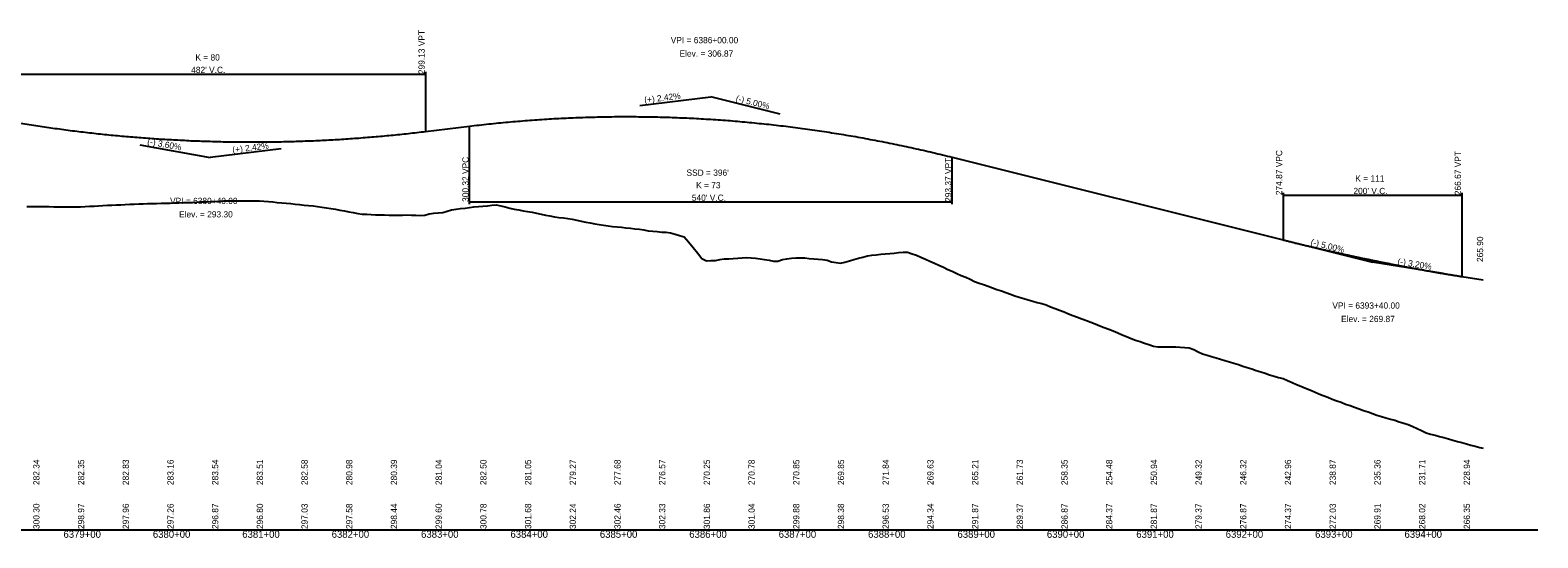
# Model space of a CAD drawing. Extents: x 1838386 to 1955906, y 719739 to 834437.
# Drawn here: x 1953520 to 1955206, y 770980 to 771548 of the extents above; entities that cross this region are included whole.
import ezdxf

# ---------------------------------------------------------------- set-up
doc = ezdxf.new("R2010")
doc.units = 0
for name, color, linetype in [('RD_DDB_GradeTX', 7, 'Continuous'), ('RD_DDB_Profile_EX', 7, 'Continuous'), ('RD_DDB_Profile_Lbl', 7, 'Continuous'), ('RD_DDB_Profile_PR', 7, 'Continuous'), ('RD_DDB_StaTX', 7, 'Continuous'), ('RD_DDB_StripGrade', 7, 'Continuous'), ('RD_DDB_VCLbl', 7, 'Continuous'), ('RD_GPK_Profile_Cell', 7, 'Continuous')]:
    doc.layers.add(name, color=color, linetype=linetype)

msp = doc.modelspace()

# ---------------------------------------------------------------- linework, layer by layer
at = {"layer": 'RD_DDB_GradeTX'}
for p, q in [((1954202, 771463.9), (1954281.4, 771473.5)), ((1954359, 771454.1), (1954281.4, 771473.5)), ((1953642.6, 771419.8), (1953721.4, 771405.6)), ((1953800.8, 771415.2), (1953721.4, 771405.6)), ((1954943.8, 771307.9), (1955021.4, 771288.5)), ((1955100.4, 771275.8), (1955021.4, 771288.5))]:
    msp.add_line(p, q, dxfattribs=at)
at = {"layer": 'RD_DDB_Profile_EX'}
for points in [[(1953516.4, 771350.7), (1953521.4, 771350.7), (1953526.4, 771350.7), (1953531.4, 771350.8), (1953536.4, 771350.7), (1953541.4, 771350.7), (1953546.4, 771350.6), (1953551.4, 771350.6), (1953556.4, 771350.6), (1953561.4, 771350.5), (1953566.4, 771350.5), (1953571.4, 771350.5), (1953576.4, 771350.6), (1953581.4, 771350.9), (1953586.4, 771351.2), (1953591.4, 771351.4), (1953596.4, 771351.7), (1953601.4, 771351.9), (1953606.4, 771352.2), (1953611.4, 771352.4), (1953616.4, 771352.6), (1953621.4, 771352.8), (1953626.4, 771353), (1953631.4, 771353.3), (1953636.4, 771353.5), (1953641.4, 771353.7), (1953646.4, 771353.9), (1953651.4, 771354.1), (1953656.4, 771354.2), (1953661.4, 771354.3), (1953666.4, 771354.4), (1953671.4, 771354.6), (1953676.4, 771354.7), (1953681.4, 771354.9), (1953686.4, 771355.1), (1953691.4, 771355.3), (1953696.4, 771355.4), (1953701.4, 771355.4), (1953706.4, 771355.6), (1953711.4, 771355.9), (1953716.4, 771356.1), (1953721.4, 771356.3), (1953726.4, 771356.6), (1953731.4, 771356.8), (1953736.4, 771357), (1953741.4, 771357.2), (1953746.4, 771357.2), (1953751.4, 771357.2), (1953756.4, 771357.1), (1953761.4, 771357), (1953766.4, 771357), (1953771.4, 771357), (1953776.4, 771357), (1953781.4, 771356.7), (1953786.4, 771356.4), (1953791.4, 771355.9), (1953796.4, 771355.4), (1953801.4, 771354.8), (1953806.4, 771354.4), (1953811.4, 771354.1), (1953816.4, 771353.6), (1953821.4, 771353.1), (1953826.4, 771352.5), (1953831.4, 771352), (1953836.4, 771351.6), (1953841.4, 771351), (1953846.4, 771350.2), (1953851.4, 771349.5), (1953856.4, 771348.7), (1953861.4, 771347.8), (1953866.4, 771346.9), (1953871.4, 771346), (1953876.4, 771345), (1953881.4, 771344), (1953886.4, 771343), (1953891.4, 771342.4), (1953896.4, 771342.1), (1953901.4, 771341.8), (1953906.4, 771341.5), (1953911.4, 771341.5), (1953916.4, 771341.4)], [(1953916.4, 771341.4), (1953921.4, 771341.2), (1953926.4, 771341.1), (1953931.4, 771341.1), (1953936.4, 771341.2), (1953941.4, 771341.4), (1953946.4, 771341.2), (1953951.4, 771341), (1953956.4, 771340.8), (1953961.4, 771341.2), (1953966.4, 771342.5), (1953971.4, 771343.4), (1953976.4, 771343.8), (1953981.4, 771344.3), (1953986.4, 771345.7), (1953991.4, 771347), (1953996.4, 771348), (1954001.4, 771348.5), (1954006.4, 771349.1), (1954011.4, 771349.7), (1954016.4, 771350.4), (1954021.4, 771350.7), (1954026.4, 771351.1), (1954031.4, 771351.6), (1954036.4, 771352.2), (1954041.4, 771352.6), (1954046.4, 771351.6), (1954051.4, 771350.4), (1954056.4, 771349.1), (1954061.4, 771347.8), (1954066.4, 771347), (1954071.4, 771346.1), (1954076.4, 771345.3), (1954081.4, 771344.4), (1954086.4, 771343.4), (1954091.4, 771342.4), (1954096.4, 771341.3), (1954101.4, 771340.3), (1954106.4, 771339.2), (1954111.4, 771338.5), (1954116.4, 771338.1), (1954121.4, 771337.6), (1954126.4, 771336.6), (1954131.4, 771335.5), (1954136.4, 771334.5), (1954141.4, 771333.4), (1954146.4, 771332.5), (1954151.4, 771331.6), (1954156.4, 771330.7), (1954161.4, 771329.9), (1954166.4, 771329.2), (1954171.4, 771328.6), (1954176.4, 771328.1), (1954181.4, 771327.6), (1954186.4, 771327), (1954191.4, 771326.5), (1954196.4, 771325.9), (1954201.4, 771325.3), (1954206.4, 771324.6), (1954211.4, 771323.8), (1954216.4, 771323.1), (1954221.4, 771322.7), (1954226.4, 771322.3), (1954231.4, 771322), (1954236.4, 771321.2), (1954241.4, 771319.8), (1954246.4, 771318.4), (1954251.4, 771317), (1954256.4, 771311.2), (1954261.4, 771305.1), (1954266.4, 771298.9), (1954271.4, 771292.7), (1954276.4, 771290), (1954281.4, 771290.4), (1954286.4, 771290.6), (1954291.4, 771291.6), (1954296.4, 771292.1), (1954301.4, 771292.3), (1954306.4, 771292.8), (1954311.4, 771293), (1954316.4, 771293.4), (1954321.4, 771293.8), (1954326.4, 771293.5), (1954331.4, 771293), (1954336.4, 771292.4), (1954341.4, 771291.7), (1954346.4, 771290.9), (1954351.4, 771289.7), (1954356.4, 771289.7), (1954361.4, 771291.6), (1954366.4, 771292.4), (1954371.4, 771293), (1954376.4, 771293.3), (1954381.4, 771293.4), (1954386.4, 771293.3), (1954391.4, 771292.8), (1954396.4, 771292.4), (1954401.4, 771291.9), (1954406.4, 771291.5), (1954411.4, 771290.8), (1954416.4, 771289.1)], [(1954416.4, 771289.1), (1954421.4, 771288.1), (1954426.4, 771287.6), (1954431.4, 771288.4), (1954436.4, 771290), (1954441.4, 771291.5), (1954446.4, 771292.9), (1954451.4, 771294.3), (1954456.4, 771295.7), (1954461.4, 771296.5), (1954466.4, 771296.9), (1954471.4, 771297.4), (1954476.4, 771297.9), (1954481.4, 771298.3), (1954486.4, 771298.8), (1954491.4, 771299.3), (1954496.4, 771299.8), (1954501.4, 771299.6), (1954506.4, 771297.9), (1954511.4, 771296.2), (1954516.4, 771294.1), (1954521.4, 771291.8), (1954526.4, 771289.6), (1954531.4, 771287.3), (1954536.4, 771285.1), (1954541.4, 771282.8), (1954546.4, 771280.5), (1954551.4, 771278.3), (1954556.4, 771276), (1954561.4, 771273.8), (1954566.4, 771271.6), (1954571.4, 771269.4), (1954576.4, 771267), (1954581.4, 771265.2), (1954586.4, 771263.4), (1954591.4, 771261.6), (1954596.4, 771259.9), (1954601.4, 771258.1), (1954606.4, 771256.3), (1954611.4, 771254.5), (1954616.4, 771252.8), (1954621.4, 771251), (1954626.4, 771249.4), (1954631.4, 771247.8), (1954636.4, 771246.4), (1954641.4, 771245), (1954646.4, 771243.6), (1954651.4, 771242.2), (1954656.4, 771240.7), (1954661.4, 771238.7), (1954666.4, 771236.7), (1954671.4, 771234.8), (1954676.4, 771232.8), (1954681.4, 771230.9), (1954686.4, 771229), (1954691.4, 771227.1), (1954696.4, 771225.3), (1954701.4, 771223.3), (1954706.4, 771221.3), (1954711.4, 771219.4), (1954716.4, 771217.4), (1954721.4, 771215.4), (1954726.4, 771213.5), (1954731.4, 771211.6), (1954736.4, 771209.5), (1954741.4, 771207.4), (1954746.4, 771205.3), (1954751.4, 771203.2), (1954756.4, 771201.4), (1954761.4, 771199.7), (1954766.4, 771198), (1954771.4, 771196.3), (1954776.4, 771194.6), (1954781.4, 771193.9), (1954786.4, 771193.9), (1954791.4, 771193.8), (1954796.4, 771193.8), (1954801.4, 771193.7), (1954806.4, 771193.4), (1954811.4, 771193.1), (1954816.4, 771192.8), (1954821.4, 771190.7), (1954826.4, 771188.1), (1954831.4, 771185.8), (1954836.4, 771184.3), (1954841.4, 771182.8), (1954846.4, 771181.4), (1954851.4, 771179.9), (1954856.4, 771178.5), (1954861.4, 771177), (1954866.4, 771175.4), (1954871.4, 771173.9), (1954876.4, 771172.3), (1954881.4, 771170.7), (1954886.4, 771169.1), (1954891.4, 771167.5), (1954896.4, 771165.9), (1954901.4, 771164.3), (1954906.4, 771162.6), (1954911.4, 771161.1), (1954916.4, 771159.5)], [(1954916.4, 771159.5), (1954921.4, 771158.3), (1954926.4, 771156.1), (1954931.4, 771153.9), (1954936.4, 771151.7), (1954941.4, 771149.6), (1954946.4, 771147.6), (1954951.4, 771145.5), (1954956.4, 771143.3), (1954961.4, 771141.3), (1954966.4, 771139.3), (1954971.4, 771137.4), (1954976.4, 771135.2), (1954981.4, 771133.5), (1954986.4, 771131.7), (1954991.4, 771129.8), (1954996.4, 771128), (1955001.4, 771126.2), (1955006.4, 771124.5), (1955011.4, 771122.7), (1955016.4, 771120.9), (1955021.4, 771119.1), (1955026.4, 771117.4), (1955031.4, 771116), (1955036.4, 771114.5), (1955041.4, 771113), (1955046.4, 771111.6), (1955051.4, 771109.9), (1955056.4, 771108.3), (1955061.4, 771106.9), (1955066.4, 771104.7), (1955071.4, 771102.3), (1955076.4, 771100), (1955081.4, 771097.7), (1955086.4, 771096.2), (1955091.4, 771095), (1955096.4, 771093.6), (1955101.4, 771092.2), (1955106.4, 771090.8), (1955111.4, 771089.4), (1955116.4, 771088), (1955121.4, 771086.6), (1955126.4, 771085.2), (1955131.4, 771083.9), (1955136.4, 771082.6), (1955141.4, 771081.3), (1955145.2, 771080.3)]]:
    msp.add_lwpolyline(points, dxfattribs=at)
at = {"layer": 'RD_DDB_Profile_PR'}
for p, q in [((1953962.3, 771434.8), (1954011.4, 771440.8)), ((1954551.4, 771406), (1954921.4, 771313.5)), ((1955121.4, 771272.5), (1955145.2, 771268.7))]:
    msp.add_line(p, q, dxfattribs=at)
for points in [[(1953480.5, 771449), (1953490.1, 771447.3), (1953499.7, 771445.6), (1953509.4, 771444), (1953519, 771442.5), (1953528.7, 771441), (1953538.3, 771439.6), (1953547.9, 771438.3), (1953557.6, 771437), (1953567.2, 771435.7), (1953576.8, 771434.5), (1953586.5, 771433.4), (1953596.1, 771432.3), (1953605.7, 771431.3), (1953615.4, 771430.4), (1953625, 771429.5), (1953634.7, 771428.7), (1953644.3, 771427.9), (1953653.9, 771427.2), (1953663.6, 771426.5), (1953673.2, 771425.9), (1953682.8, 771425.4), (1953692.5, 771424.9), (1953702.1, 771424.4), (1953711.7, 771424.1), (1953721.4, 771423.8), (1953731, 771423.5), (1953740.6, 771423.3), (1953750.3, 771423.2), (1953759.9, 771423.1), (1953769.6, 771423.1), (1953779.2, 771423.1), (1953788.8, 771423.2), (1953798.5, 771423.3), (1953808.1, 771423.6), (1953817.7, 771423.8), (1953827.4, 771424.2), (1953837, 771424.5), (1953846.6, 771425), (1953856.3, 771425.5), (1953865.9, 771426), (1953875.5, 771426.7), (1953885.2, 771427.3), (1953894.8, 771428.1), (1953904.5, 771428.9), (1953914.1, 771429.7), (1953923.7, 771430.6), (1953933.4, 771431.6), (1953943, 771432.6), (1953952.6, 771433.7), (1953962.3, 771434.8)], [(1954011.4, 771440.8), (1954022.2, 771442), (1954033, 771443.2), (1954043.8, 771444.3), (1954054.6, 771445.4), (1954065.4, 771446.3), (1954076.2, 771447.2), (1954087, 771448), (1954097.8, 771448.7), (1954108.6, 771449.3), (1954119.4, 771449.8), (1954130.2, 771450.3), (1954141, 771450.7), (1954151.8, 771451), (1954162.6, 771451.2), (1954173.4, 771451.4), (1954184.2, 771451.4), (1954195, 771451.4), (1954205.8, 771451.3), (1954216.6, 771451.2), (1954227.4, 771450.9), (1954238.2, 771450.6), (1954249, 771450.1), (1954259.8, 771449.7), (1954270.6, 771449.1), (1954281.4, 771448.4), (1954292.2, 771447.7), (1954303, 771446.9), (1954313.8, 771446), (1954324.6, 771445), (1954335.4, 771443.9), (1954346.2, 771442.8), (1954357, 771441.6), (1954367.8, 771440.3), (1954378.6, 771438.9), (1954389.4, 771437.5), (1954400.2, 771435.9), (1954411, 771434.3), (1954421.8, 771432.6), (1954432.6, 771430.8), (1954443.4, 771429), (1954454.2, 771427), (1954465, 771425), (1954475.8, 771422.9), (1954486.6, 771420.7), (1954497.4, 771418.5), (1954508.2, 771416.1), (1954519, 771413.7), (1954529.8, 771411.2), (1954540.6, 771408.6), (1954551.4, 771406)], [(1954921.4, 771313.5), (1954925.4, 771312.5), (1954929.4, 771311.5), (1954933.4, 771310.5), (1954937.4, 771309.5), (1954941.4, 771308.6), (1954945.4, 771307.6), (1954949.4, 771306.7), (1954953.4, 771305.7), (1954957.4, 771304.8), (1954961.4, 771303.8), (1954965.4, 771302.9), (1954969.4, 771302), (1954973.4, 771301.1), (1954977.4, 771300.2), (1954981.4, 771299.3), (1954985.4, 771298.4), (1954989.4, 771297.5), (1954993.4, 771296.6), (1954997.4, 771295.8), (1955001.4, 771294.9), (1955005.4, 771294.1), (1955009.4, 771293.2), (1955013.4, 771292.4), (1955017.4, 771291.6), (1955021.4, 771290.7), (1955025.4, 771289.9), (1955029.4, 771289.1), (1955033.4, 771288.3), (1955037.4, 771287.5), (1955041.4, 771286.7), (1955045.4, 771285.9), (1955049.4, 771285.2), (1955053.4, 771284.4), (1955057.4, 771283.6), (1955061.4, 771282.9), (1955065.4, 771282.1), (1955069.4, 771281.4), (1955073.4, 771280.7), (1955077.4, 771280), (1955081.4, 771279.2), (1955085.4, 771278.5), (1955089.4, 771277.8), (1955093.4, 771277.1), (1955097.4, 771276.4), (1955101.4, 771275.8), (1955105.4, 771275.1), (1955109.4, 771274.4), (1955113.4, 771273.8), (1955117.4, 771273.1), (1955121.4, 771272.5)]]:
    msp.add_spline(points, degree=3, dxfattribs=at)
at = {"layer": 'RD_DDB_VCLbl'}
for p, q in [((1953480.5, 771499), (1953962.3, 771499)), ((1953962.3, 771501.5), (1953962.3, 771434.8)), ((1954011.4, 771353.5), (1954011.4, 771440.8)), ((1954551.4, 771353.5), (1954551.4, 771406)), ((1954921.4, 771366), (1954921.4, 771313.5)), ((1954921.4, 771363.5), (1955121.4, 771363.5)), ((1955121.4, 771366), (1955121.4, 771272.5)), ((1954011.4, 771356), (1954551.4, 771356))]:
    msp.add_line(p, q, dxfattribs=at)
at = {"layer": 'RD_GPK_Profile_Cell'}
msp.add_line((1951406.4, 770989.1), (1955206.4, 770989.1), dxfattribs=at)

# ---------------------------------------------------------------- texts
at = {"layer": 'RD_DDB_GradeTX'}
for s, rotation, p in [('(+) 2.42%', 6.9088, (1954207.3, 771466.5)), ('(-) 5.00%', 345.9638, (1954308.7, 771468.7)), ('(-) 3.60%', 349.796, (1953650.6, 771420.4)), ('(+) 2.42%', 6.9088, (1953746.6, 771410.7)), ('(-) 5.00%', 345.9638, (1954951.7, 771308)), ('(-) 3.20%', 350.9097, (1955049, 771286.1))]:
    msp.add_text(s, height=7, rotation=rotation, dxfattribs=at).set_placement(p)
at = {"layer": 'RD_DDB_Profile_Lbl'}
for s, p in [('VPI = 6386+00.00', (1954236.5, 771533.5)), ('Elev. = 306.87', (1954246.3, 771518.5)), ('VPI = 6380+40.00', (1953676.5, 771353.6)), ('Elev. = 293.30', (1953686.5, 771338.6)), ('VPI = 6393+40.00', (1954976.5, 771236.5)), ('Elev. = 269.87', (1954986.3, 771221.5))]:
    msp.add_text(s, height=7, dxfattribs=at).set_placement(p)
msp.add_text('265.90', height=7, rotation=90, dxfattribs=at).set_placement((1955145.2, 771288.7))
at = {"layer": 'RD_DDB_StaTX'}
for s, p in [('6379+00', (1953557.2, 770980.1)), ('6380+00', (1953657.2, 770980.1)), ('6381+00', (1953757.2, 770980.1)), ('6382+00', (1953857.2, 770980.1)), ('6383+00', (1953957.2, 770980.1)), ('6384+00', (1954057.2, 770980.1)), ('6385+00', (1954157.2, 770980.1)), ('6386+00', (1954257.2, 770980.1)), ('6387+00', (1954357.2, 770980.1)), ('6388+00', (1954457.2, 770980.1)), ('6389+00', (1954557.2, 770980.1)), ('6390+00', (1954657.2, 770980.1)), ('6391+00', (1954757.2, 770980.1)), ('6392+00', (1954857.2, 770980.1)), ('6393+00', (1954957.2, 770980.1)), ('6394+00', (1955057.2, 770980.1))]:
    msp.add_text(s, height=8, dxfattribs=at).set_placement(p)
at = {"layer": 'RD_DDB_StripGrade'}
for s, p in [('299.13 VPT', (1953961.3, 771499)), ('274.87 VPC', (1954920.4, 771363.5)), ('266.67 VPT', (1955120.4, 771363.5)), ('300.32 VPC', (1954010.4, 771356)), ('293.37 VPT', (1954550.4, 771356)), ('282.34', (1953530.4, 771039.1)), ('282.35', (1953580.4, 771039.1)), ('282.83', (1953630.4, 771039.1)), ('283.16', (1953680.4, 771039.1)), ('283.54', (1953730.4, 771039.1)), ('283.51', (1953780.4, 771039.1)), ('282.58', (1953830.4, 771039.1)), ('280.98', (1953880.4, 771039.1)), ('280.39', (1953930.4, 771039.1)), ('281.04', (1953980.4, 771039.1)), ('282.50', (1954030.4, 771039.1)), ('281.05', (1954080.4, 771039.1)), ('279.27', (1954130.4, 771039.1)), ('277.68', (1954180.4, 771039.1)), ('276.57', (1954230.4, 771039.1)), ('270.25', (1954280.4, 771039.1)), ('270.78', (1954330.4, 771039.1)), ('270.85', (1954380.4, 771039.1)), ('269.85', (1954430.4, 771039.1)), ('271.84', (1954480.4, 771039.1)), ('269.63', (1954530.4, 771039.1)), ('265.21', (1954580.4, 771039.1)), ('261.73', (1954630.4, 771039.1)), ('258.35', (1954680.4, 771039.1)), ('254.48', (1954730.4, 771039.1)), ('250.94', (1954780.4, 771039.1)), ('249.32', (1954830.4, 771039.1)), ('246.32', (1954880.4, 771039.1)), ('242.96', (1954930.4, 771039.1)), ('238.87', (1954980.4, 771039.1)), ('235.36', (1955030.4, 771039.1)), ('231.71', (1955080.4, 771039.1)), ('228.94', (1955130.4, 771039.1)), ('300.30', (1953530.4, 770989.9)), ('298.97', (1953580.4, 770989.9)), ('297.96', (1953630.4, 770989.9)), ('297.26', (1953680.4, 770989.9)), ('296.87', (1953730.4, 770989.9)), ('296.80', (1953780.4, 770989.9)), ('297.03', (1953830.4, 770989.9)), ('297.58', (1953880.4, 770989.9)), ('298.44', (1953930.4, 770989.9)), ('299.60', (1953980.4, 770989.9)), ('300.78', (1954030.4, 770989.9)), ('301.68', (1954080.4, 770989.9)), ('302.24', (1954130.4, 770989.9)), ('302.46', (1954180.4, 770989.9)), ('302.33', (1954230.4, 770989.9)), ('301.86', (1954280.4, 770989.9)), ('301.04', (1954330.4, 770989.9)), ('299.88', (1954380.4, 770989.9)), ('298.38', (1954430.4, 770989.9)), ('296.53', (1954480.4, 770989.9)), ('294.34', (1954530.4, 770989.9)), ('291.87', (1954580.4, 770989.9)), ('289.37', (1954630.4, 770989.9)), ('286.87', (1954680.4, 770989.9)), ('284.37', (1954730.4, 770989.9)), ('281.87', (1954780.4, 770989.9)), ('279.37', (1954830.4, 770989.9)), ('276.87', (1954880.4, 770989.9)), ('274.37', (1954930.4, 770989.9)), ('272.03', (1954980.4, 770989.9)), ('269.91', (1955030.4, 770989.9)), ('268.02', (1955080.4, 770989.9)), ('266.35', (1955130.4, 770989.9))]:
    msp.add_text(s, height=7, rotation=90, dxfattribs=at).set_placement(p)
at = {"layer": 'RD_DDB_VCLbl'}
for s, p in [('K = 80', (1953704.8, 771514.2)), ("482' V.C.", (1953700.1, 771500.2)), ("SSD = 396'", (1954254.1, 771385.2)), ('K = 73', (1954264.9, 771371.2)), ('K = 111', (1955002.2, 771378.7)), ("540' V.C.", (1954260.1, 771357.2)), ("200' V.C.", (1955000.1, 771364.7))]:
    msp.add_text(s, height=7, dxfattribs=at).set_placement(p)

doc.saveas('drawing.dxf')
